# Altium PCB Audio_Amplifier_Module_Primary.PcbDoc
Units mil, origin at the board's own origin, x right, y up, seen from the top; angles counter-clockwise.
Board outline 3150 x 1535 mil, 2 copper layers (Top Layer, Bottom Layer); 30 components, 23 nets, 71 pads, 14 vias.
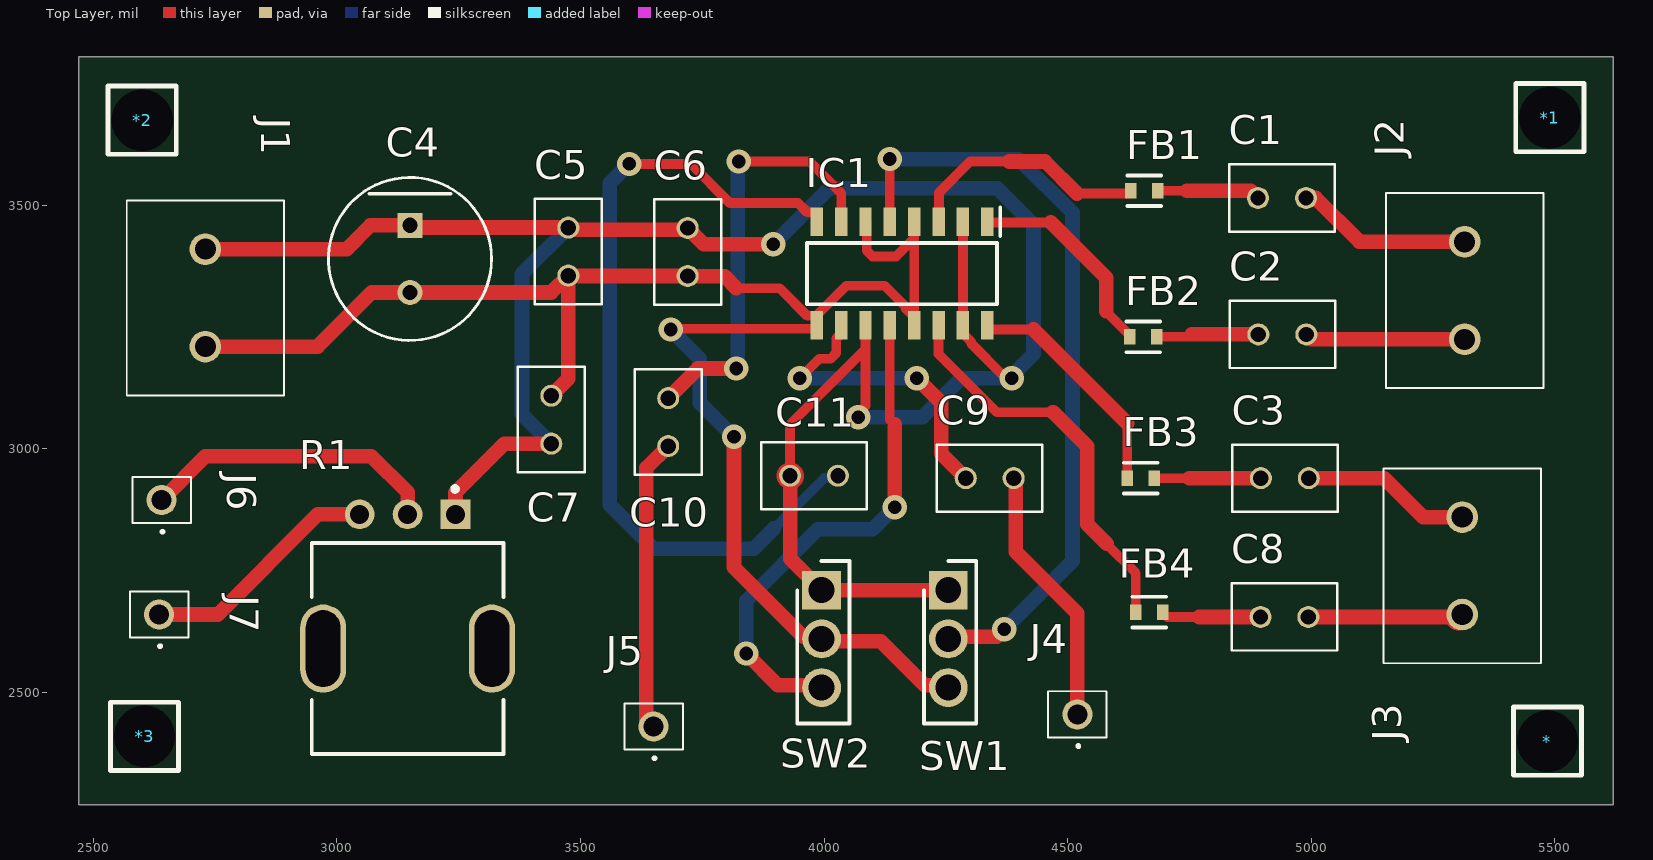
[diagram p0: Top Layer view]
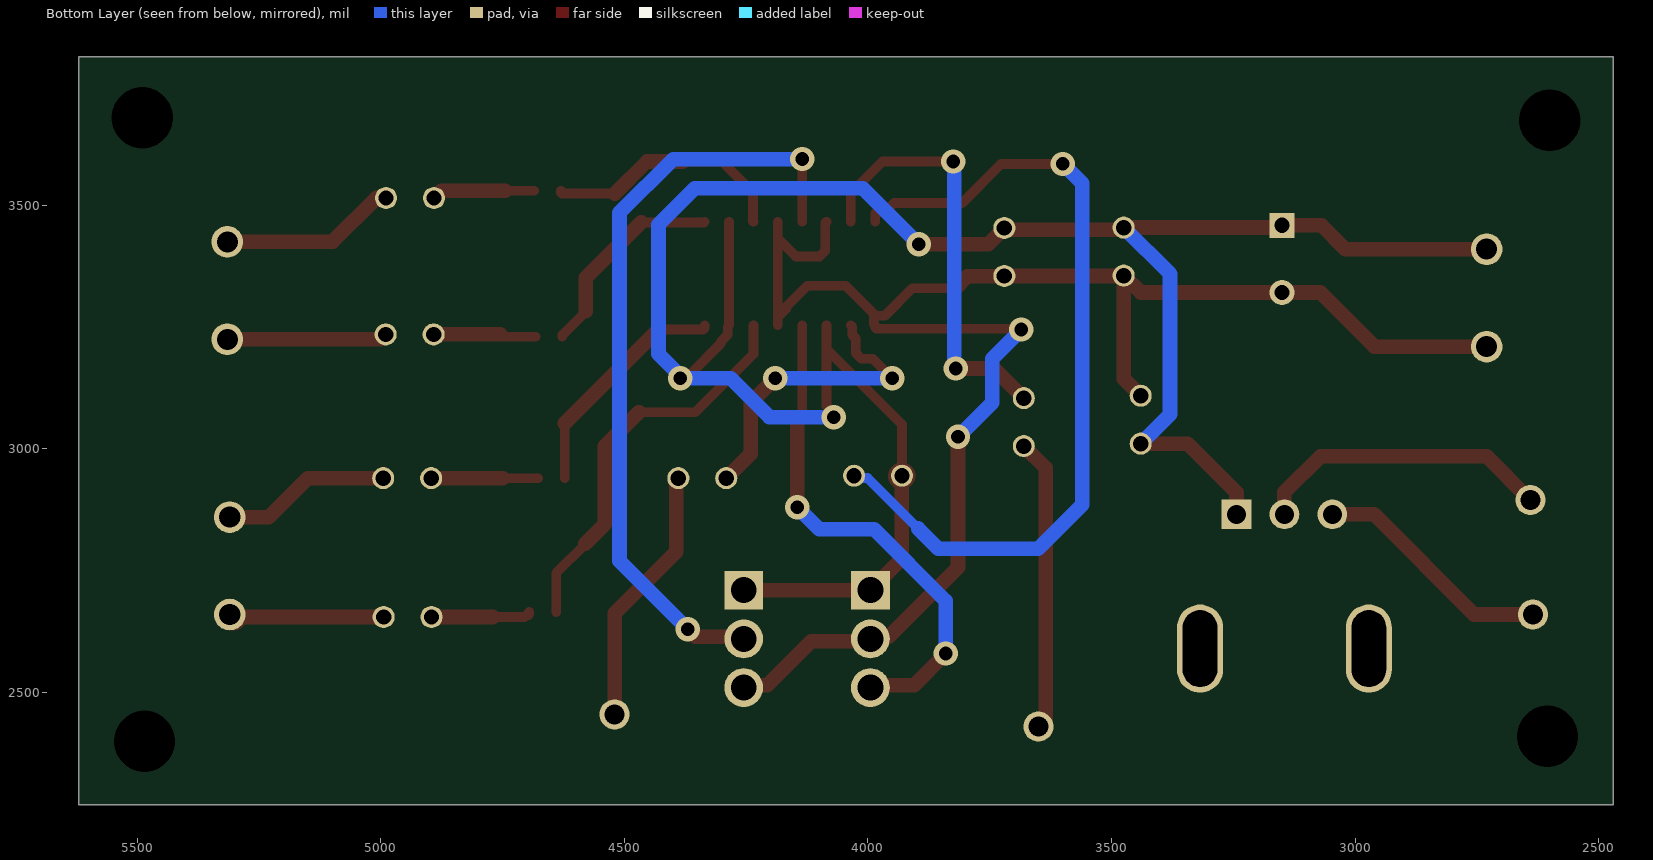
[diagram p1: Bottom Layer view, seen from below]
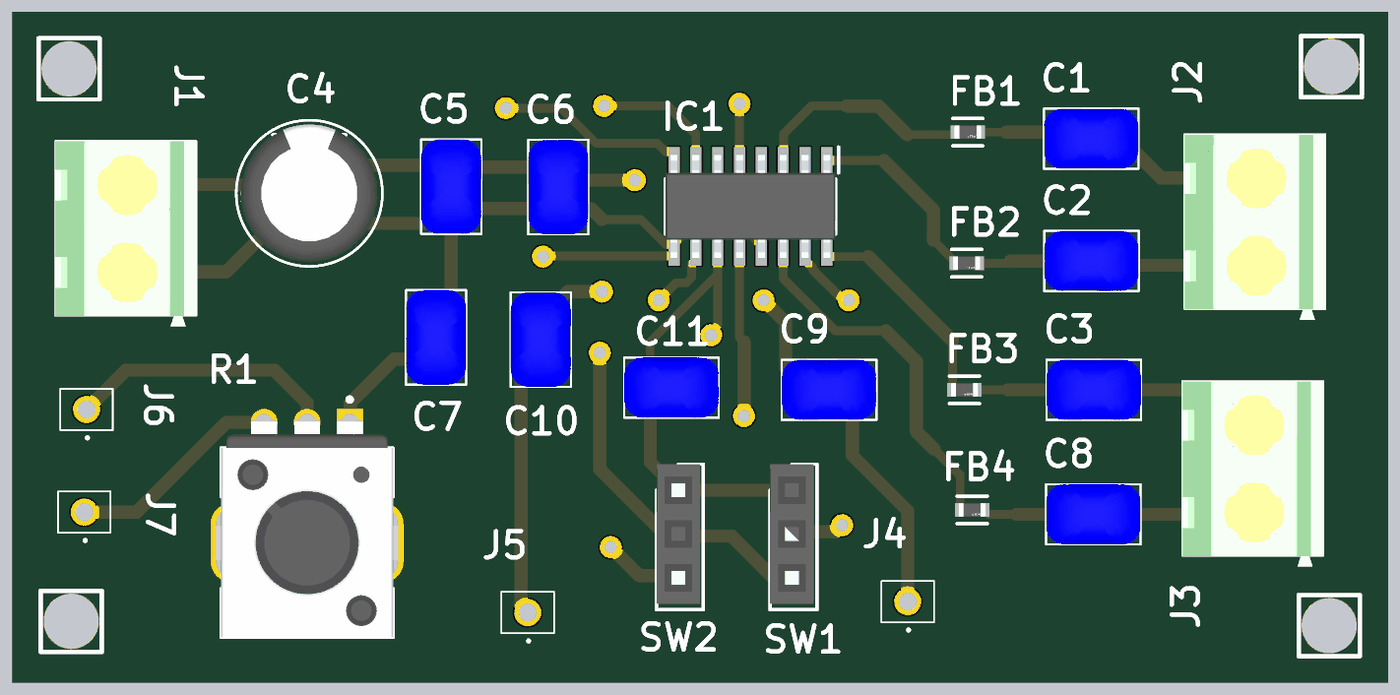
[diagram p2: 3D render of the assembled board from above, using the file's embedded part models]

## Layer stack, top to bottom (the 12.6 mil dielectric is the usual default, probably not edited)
Top Solder: solder mask 0.4, Solder Resist, Dk 3.5
Top Layer: signal copper 1.4
Dielectric 1: dielectric 12.6, FR-4, Dk 4.8
Bottom Layer: signal copper 1.4
Bottom Solder: solder mask 0.4, Solder Resist, Dk 3.5

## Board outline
2470,2270 5620,2270 5620,3805 2470,3805

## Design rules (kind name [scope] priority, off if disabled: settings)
Clearance [All] p1: gap=10 ignorepadtopadclearanceinfootprint=FALSE
PolygonConnect [All] p1: connectstyle=Relief reliefconductorwidth=10 reliefentries=4 polygonreliefangle="90 Angle" airgapwidth=10
RoutingVias [All] p1: holewidth=28 width=50 viastyle="Through Hole" minholewidth=28 minwidth=50 maxholewidth=28 maxwidth=50
SolderMaskExpansion [All] p1: expansion=4 istentingtop=FALSE
SupplyNets "Schematic Supply Nets" [InNet('GND')] p1: voltage=0.000
Width [All] p1: maxlimit=55 minlimit=10 preferedwidth=20
30 further rules are at their usual default settings.

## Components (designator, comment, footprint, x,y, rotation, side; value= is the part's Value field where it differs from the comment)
* "Mounting Hole" MTHNP3P2MM 5485,2400 r0 top
*1 "Mounting Hole" MTHNP3P2MM 5490,3680 r0 top
*2 "Mounting Hole" MTHNP3P2MM 2600,3675 r0 top
*3 "Mounting Hole" MTHNP3P2MM 2605,2410 r0 top
C1 "FA16X7R1E106KRU00" CAPRB250W50L550T350H600 4940,3515 r0 top
C2 "FA16X7R1E106KRU00" CAPRB250W50L550T350H600 4940.79,3235 r0 top
C3 "FA16X7R1E106KRU00" CAPRB250W50L550T350H600 4945.79,2940 r0 top
C4 "20uF" FP-EEU-FR1H101B-MFG 3150,3390 r270 top value=100uF
C5 "1uF" CAPRB250W50L550T350H600 3475,3405 r270 top
C6 "1uF" CAPRB250W50L550T350H600 3720,3404.21 r270 top
C7 "1uF" CAPRB250W50L550T350H600 3440,3060 r90 top
C8 "FA16X7R1E106KRU00" CAPRB250W50L550T350H600 4945,2655 r0 top
C9 "FA16X7R1E106KRU00" CAPRB250W50L550T350H600 4340,2940 r0 top
C10 "FA16X7R1E106KRU00" CAPRB250W50L550T350H600 3680,3055 r270 top
C11 "1uF" CAPRB250W50L550T350H600 3979.21,2945 r0 top
FB1 "MPZ1608S221ATA00" FP-MPZ1608-0_8-MFG 4657.56,3530 r0 top
FB2 "MPZ1608S221ATA00" FP-MPZ1608-0_8-MFG 4655,3230 r0 top
FB3 "MPZ1608S221ATA00" FP-MPZ1608-0_8-MFG 4650,2940 r0 top
FB4 "MPZ1608S221ATA00" FP-MPZ1608-0_8-MFG 4667.56,2665 r0 top
IC1 "PAM8406DR" SOIC127P600X126-16N 4160,3360 r270 top
J1 "282837-2" 2828372 2730,3410 r270 top
J2 "282837-2" 2828372 5315,3425 r270 top
J3 "282837-2" 2828372 5310,2860 r270 top
J4 "SSW-101-01-T-S" SSW-101-XX-YYY-S 4520,2455 r0 top
J5 "SSW-101-01-T-S" SSW-101-XX-YYY-S 3650,2430 r0 top
J6 "SSW-101-01-T-S" SSW-101-XX-YYY-S 2640,2895 r0 top
J7 "SSW-101-01-T-S" SSW-101-XX-YYY-S 2635,2660 r0 top
R1 "PTV09A-4225F-B103" FP-PTV09A-4-MFG 3145,2590 r180 top value=10kR
SW1 "PPTC031LFBN-RC" RHDR3W80P0X254_1X3_812X254X850P 4255,2710 r270 top
SW2 "PPTC031LFBN-RC" RHDR3W80P0X254_1X3_812X254X850P 3995,2710 r270 top

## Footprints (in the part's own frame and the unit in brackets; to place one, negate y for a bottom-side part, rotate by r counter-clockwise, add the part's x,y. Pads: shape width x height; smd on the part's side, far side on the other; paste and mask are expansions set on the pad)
2828372 [mm]
  round 1.65 hole 1.1: 1(0,0) 2(5.08,0)
  silkscreen extent -2.54,-4.1 7.62,4.1, body extent -2.51,-4.11 8.25,4.09, height 9.84
CAPRB250W50L550T350H600 [mm]
  round 1.15 hole 0.8: 1(-1.25,0) 2(1.25,0)
  silkscreen extent -2.75,-1.75 2.75,1.75, body extent -2.75,-1.75 2.75,1.75, height 3
FP-EEU-FR1H101B-MFG [mm]
  rect 1.3x1.3 hole 0.8 paste-2539.97 mask+0: 1(-1.75,0)
  round 1.3 hole 0.8 paste-2539.97 mask+0: 2(1.75,0)
  silkscreen extent -4.25,-4.25 4.25,4.25, body extent -4.35,-4.35 4.35,4.35, height 0.25
FP-MPZ1608-0_8-MFG [mm]
  rect 0.6x0.8 smd paste+0 mask+0: 1(-0.7,0) 2(0.7,0)
  silkscreen extent -0.87,-0.8 0.87,0.8, body extent -1.1,-0.58 1.1,0.58, height 0.25
FP-PTV09A-4-MFG [mm]
  rect 1.55x1.55 hole 1 paste-2539.97 mask+0: 1(-2.5,-7)
  round 1.55 hole 1 paste-2539.97 mask+0: 2(0,-7) 3(2.5,-7)
  rrect100% 2.4x4.6 hole 4 slot 1.8 at 0 deg paste-2539.97 mask+0: 4(-4.4,0) 5(4.4,0)
  silkscreen extent -5,-8.45 5,5.5, body extent -5.8,-7.88 5.8,5.6, height 0.25
MTHNP3P2MM [mm] "Mounting Hole Non-Plated 3.2mm"
  round 0 hole 3.2: ""(0,0)
  silkscreen extent -1.78,-1.78 1.78,1.78
RHDR3W80P0X254_1X3_812X254X850P [mm]
  rect 2.025x2.025 hole 1.35: 1(0,0)
  round 2.025 hole 1.35: 2(2.54,0) 3(5.08,0)
  silkscreen extent -1.52,-1.27 6.95,1.46, body extent -1.52,-1.27 6.6,1.27, height 8.5
SOIC127P600X126-16N [mm]
  rect 1.5x0.65 smd: 1(-2.7,4.445) 2(-2.7,3.175) 3(-2.7,1.905) 4(-2.7,0.635) 5(-2.7,-0.635) 6(-2.7,-1.905) 7(-2.7,-3.175) 8(-2.7,-4.445) 9(2.7,-4.445) 10(2.7,-3.175) 11(2.7,-1.905) 12(2.7,-0.635) 13(2.7,0.635) 14(2.7,1.905) 15(2.7,3.175) 16(2.7,4.445)
  silkscreen extent -3.45,-4.95 1.6,5.12, body extent -3,-4.95 3,4.95, height 1.26
SSW-101-XX-YYY-S [mm]
  round 1.57 hole 1.04: 1(0,0)
  silkscreen extent -1.53,-1.7 1.53,1.2

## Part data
C1 C2 C3 C8 C9 C10: library part CMP-030-000002-1, "10 ÂµF Â±10% 25V Ceramic Capacitor X7R Radial", Package="Radial TDK"
C4: library part CMP-05427-000020-1, "CAP ALUM 100UF 20% 50V RADIAL", Capacitance=100uF, Case/Package=Radial, ESR (Equivalent Series Resistance)=61mR, Max Operating Temperature=105°C, Min Operating Temperature=-40°C, Package Quantity=1, Ripple Current=870mA, Tolerance=20%, Voltage Rating=50V
C5 C6 C7 C11: library part CMP-030-000003-1, "1 ÂµF Â±10% 25V Ceramic Capacitor X7R Radial", Package="Radial TDK"
FB1 FB2 FB3 FB4: library part CMP-08257-000028-1, "Power line Ferrite Bead 220Ω @ 100MHz 2.2A DCR 0.05Ω SMD 0603", Case Code (Imperial)=0603, Case Code (Metric)=1608, Current Rating=2.2A, DC Resistance (DCR)=50mR, Package Quantity=1, Tolerance=25%
IC1: library part CMP-005-000000-1, "DiodesZetex PAM8406DR 2-Channel Audio Amplifier", Manufacturer_Name="Diodes Incorporated", Mouser Part Number=621-PAM8406DR
J1 J2 J3: "Connector", Manufacturer_Name="TE Connectivity", Mouser Part Number=571-2828372
J4 J5 J6 J7: "Connector", Manufacturer_Name=SAMTEC, Mouser Part Number=200-SSW10101TS
R1: library part CMP-00002-1, "Rotary Potentiometer, Carbon Element, 10 kOhm, 1Turn, Linear, 50 mW, ± 20%", Max Operating Temperature=50°C, Max Power Dissipation=50mW, Min Operating Temperature=-10°C, Package Quantity=100, Resistance Tolerance=20%, Resistor Type=Carbon
SW1 SW2: "Connector", Manufacturer_Name=Sullins

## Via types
v1: diameter 50, hole 28, Top Layer to Bottom Layer, 14 vias

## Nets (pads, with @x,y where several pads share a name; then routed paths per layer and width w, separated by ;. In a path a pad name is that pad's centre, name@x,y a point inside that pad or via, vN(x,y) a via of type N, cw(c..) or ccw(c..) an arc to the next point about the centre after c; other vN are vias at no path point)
GND: C4.1 C5.1 C6.1 C7.1 C11.1 IC1.2 IC1.11 IC1.15 J1.1 R1.1 SW1.1 SW2.1 | length 4702.5
  Top Layer w20: C11.1 3930,3050 4085,3205 ; v1(4070,3065) 4070,3073.12 4085,3088.12 4085,3205 ; IC1.11 4085,3205 ; IC1.2 IC1.15 4287.8,3250.91 4287.8,3234.17 4302.2,3219.76 4302.2,3215.89 4367.35,3150.74 4379.26,3150.74 v1(4385,3145)
  Top Layer w30: J1.1 3020,3410 3068.9,3458.9 C4.1 3154.49,3454.41 C5.1@3475,3454.41 ; R1.1 3243.43,2910.59 3343.62,3010.79 C7.1 ; C5.1 3477.92,3451.29 3488.72,3451.29 3490.29,3449.72 3712.17,3449.72 3715.87,3453.43 C6.1 ; C6.1@3719.21,3454.21 C6.1 ; v1(3895.41,3420) 3753.43,3420 C6.1 ; C11.1@3930.79,2944.21 3930.79,2774.21 SW2.1 SW1.1
  Top Layer w55: C11.1 C11.1@3930.79,2944.21
  Bottom Layer w30: C7.1 3379.86,3070.93 3379.86,3359.07 C5.1 ; v1(3895.41,3420) 4010.41,3535 4355,3535 4430,3460 4430,3195.41 4385,3150.41 v1(4385,3145) 4281.92,3145 4201.92,3065 v1(4070,3065)
NetC1_1: C1.1 FB1.2 | length 211.9
  Top Layer w20: FB1.2 4745,3530
  Top Layer w30: 4745,3530 4875.79,3530 C1.1
NetC1_2: C1.2 J2.1 | length 363.1
  Top Layer w30: C1.2 5009.21,3515 5099.21,3425 J2.1
NetC2_1: C2.1 FB2.2 | length 211.1
  Top Layer w20: FB2.2 4750,3230 4755,3235
  Top Layer w30: 4755,3235 C2.1
NetC2_2: C2.2 J2.2 | length 329.1
  Top Layer w30: C2.2 5000,3225 J2.2
NetC3_1: C3.1 FB3.2 | length 219.8
  Top Layer w20: FB3.2@4676.81,2940 4750,2940
  Top Layer w30: 4750,2940 C3.1
NetC3_2: C3.2 J3.1 | length 348.1
  Top Layer w30: C3.2 5150,2940 5230,2860 J3.1
NetC4_2: C4.2 C5.2 C6.2 C7.2 IC1.4 IC1.6 IC1.9 IC1.13 J1.2 SW1.3 SW2.2 | length 3666.3
  Top Layer w20: v1(3685,3245) 3686.5,3246.5 3982.2,3246.5 3985,3249.29 IC1.9 3987.8,3256.5 3987.8,3277.1 4045.69,3335 4124.31,3335 4168.06,3291.25 4168.06,3287.37 IC1.13@4185,3270.43 ; 3820,3330 3908.7,3330 3965.47,3273.23 3982.2,3273.23 IC1.9@3985,3270.43 ; IC1.6 4087.8,3463.5 4087.8,3406.72 4099.51,3395 4148.11,3395 4185,3431.89 ; IC1.13 IC1.13@4185,3270.43 ; IC1.4 4185,3431.89 ; IC1.13@4185,3270.43 4185,3431.89
  Top Layer w30: J1.2 2960,3210 3071.1,3321.1 C4.2 3440.32,3321.1 C5.2 3475,3144.21 C7.2 ; C5.2@3475.79,3355 C6.2 3720.79,3354.21 3795.79,3354.21 3820,3330 ; v1(3815,3025) 3815,2757.24 3957.51,2614.73 SW2.2@3990.27,2614.73 ; SW2.2@3999.73,2605.27 4116.42,2605.27 4206.96,2514.73 SW1.3@4250.27,2514.73
  Top Layer w55: SW2.2@3990.27,2614.73 SW2.2 SW2.2@3999.73,2605.27 ; SW1.3@4250.27,2514.73 SW1.3
  Bottom Layer w30: v1(3685,3245) 3745,3185 3745,3095 v1(3815,3025)
NetC8_1: C8.1 FB4.2 | length 207.1
  Top Layer w20: FB4.2 4695.12,2661.06 4696.93,2659.25 4700.87,2659.25 4705.12,2655 4770,2655
  Top Layer w30: 4770,2655 C8.1
NetC8_2: C8.2 J3.2 | length 317.9
  Top Layer w30: C8.2 J3.2@5302.3,2655
  Top Layer w55: J3.2@5302.3,2655 5307.3,2660 J3.2
NetC9_1: C9.1 IC1.10 | length 644.3
  Top Layer w20: v1(3950,3145) 3990,3185 4013.28,3185 4025,3196.72 4025,3226.97 4032.2,3234.17 4032.2,3250.91 IC1.10
  Top Layer w30: v1(4190,3145) 4240.39,3094.61 4240.39,2990.39 C9.1
  Bottom Layer w30: v1(3950,3145) v1(4190,3145)
NetC9_2: C9.2 J4.1 | length 539.2
  Top Layer w30: C9.2 4393.43,2935.79 4393.43,2789.21 4520,2662.63 J4.1
NetC10_1: C10.1 IC1.7 | length 887.9
  Top Layer w20: v1(3825,3590) 3970,3590 4035,3525 IC1.7
  Top Layer w30: C10.1 3740.79,3165 v1(3820,3165)
  Bottom Layer w30: v1(3820,3165) 3822.5,3167.5 3822.5,3587.5 v1(3825,3590)
NetC10_2: C10.2 J5.1 | length 600.6
  Top Layer w30: J5.1 3635,2445 3635,2960.79 C10.2
NetC11_2: C11.2 IC1.8 | length 1728.4
  Top Layer w20: v1(3600,3585) 3726.36,3585 3806.36,3505 3946.3,3505 3965.47,3485.83 3982.2,3485.83 3985,3483.03 IC1.8
  Bottom Layer w20: 3896.87,2836.55 4000.48,2940.16 4023.59,2940.16 C11.2
  Bottom Layer w30: v1(3600,3585) 3560,3545 3560,2885 3650,2795 3855.32,2795 3896.87,2836.55
NetFB1_1: FB1.1 IC1.3 | length 512.5
  Top Layer w20: IC1.3 4235.83,3467.13 4235.83,3525.83 4300,3590 4380,3590 ; 4519.25,3524.25 4628.19,3524.25 4630,3526.06 FB1.1
  Top Layer w30: 4380,3590 4453.5,3590 4519.25,3524.25
NetFB2_1: FB2.1 IC1.1 | length 432.8
  Top Layer w20: IC1.1 4336.3,3465 4465,3465 ; 4578.94,3282.44 4627.44,3233.94 FB2.1
  Top Layer w30: 4465,3465 4578.94,3351.06 4578.94,3282.44
NetFB3_1: FB3.1 IC1.16 | length 486.8
  Top Layer w20: IC1.16 4335,3247.8 4337.8,3245 4430,3245 ; FB3.1 4622.44,3052.56
  Top Layer w30: 4430,3245 4622.44,3052.56
NetFB4_1: FB4.1 IC1.14 | length 823.8
  Top Layer w20: IC1.14 4235,3195 4355,3075 4470,3075 ; 4580,2805 4640,2745 FB4.1
  Top Layer w30: 4470,3075 4540,3005 4540,2845 4580,2805
NetIC1_5: IC1.5 SW1.2 | length 1585.5
  Top Layer w20: IC1.5 v1(4135,3595)
  Top Layer w30: SW1.2@4259.73,2614.73 4354.73,2614.73 v1(4370,2630)
  Top Layer w55: SW1.2 SW1.2@4259.73,2614.73
  Bottom Layer w30: v1(4135,3595) 4400,3595 4510,3485 4510,2770 v1(4370,2630)
NetIC1_12: IC1.12 SW2.3 | length 1060.9
  Top Layer w20: IC1.12 4135,3060 4145,3050
  Top Layer w30: v1(3840,2580) 3905.27,2514.73 SW2.3@3990.27,2514.73 ; v1(4145,2880) 4145,3050
  Top Layer w55: SW2.3@3988.31,2510 SW2.3 SW2.3@3990.27,2514.73
  Bottom Layer w30: v1(3840,2580) 3840,2687.76 3987.24,2835 4100,2835 v1(4145,2880)
NetJ6_1: J6.1 R1.2 | length 618.1
  Top Layer w30: J6.1 2730,2985 3070.59,2985 3145,2910.59 R1.2
NetJ7_1: J7.1 R1.3 | length 496.7
  Top Layer w30: J7.1 2755,2660 2960.59,2865.59 R1.3
pads on no net: *1. *2. *3. *. R1.4 R1.5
